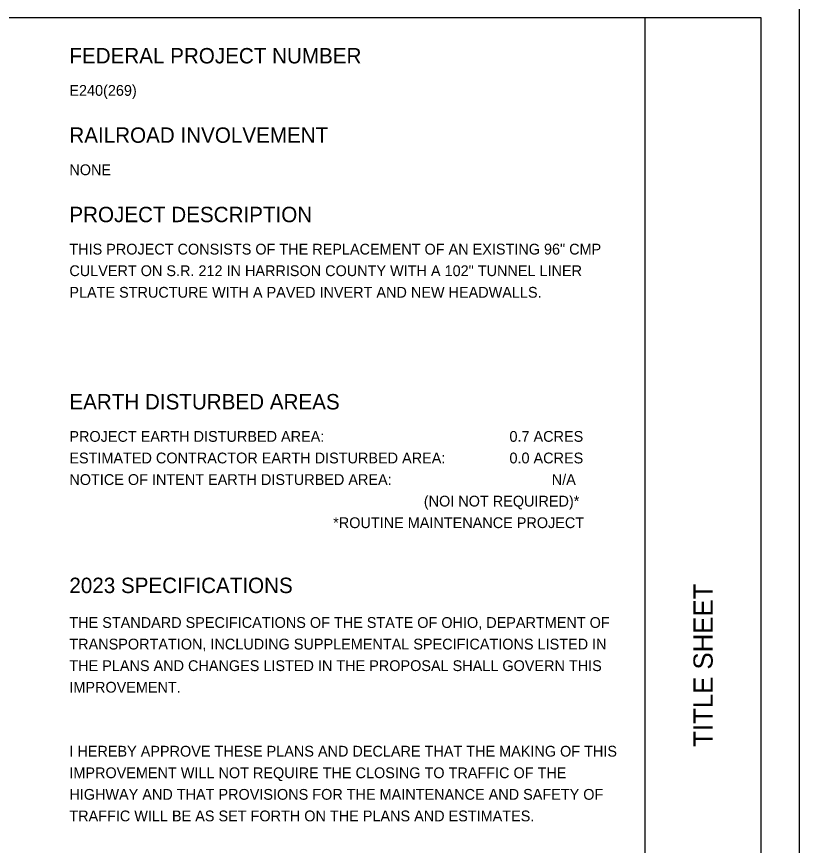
# Model space of a CAD drawing. Extents: x -19.9 to 41.9, y 0 to 32.3.
# Drawn here: x 23.84 to 34, y 10.76 to 21.51 of the extents above; entities that cross this region are included whole.
import ezdxf

# ---------------------------------------------------------------- set-up
doc = ezdxf.new("R2010")
doc.units = 0
for name, color, linetype in [('SH_Border', 7, 'Continuous'), ('SH_Cut_Line', 7, 'Continuous'), ('SH_Data', 7, 'Continuous'), ('SH_Text', 7, 'Continuous')]:
    doc.layers.add(name, color=color, linetype=linetype)

msp = doc.modelspace()

# ---------------------------------------------------------------- linework, layer by layer
at = {"layer": 'SH_Border'}
msp.add_line((32, 0.5), (32, 21.5), dxfattribs=at)
msp.add_lwpolyline([(1.5, 21.5), (33.5, 21.5), (33.5, 0.5), (1.5, 0.5)], close=True, dxfattribs=at)
at = {"layer": 'SH_Cut_Line'}
msp.add_lwpolyline([(0, 0), (34, 0), (34, 22), (0, 22)], close=True, dxfattribs=at)

# ---------------------------------------------------------------- texts
at = {"layer": 'SH_Data'}
msp.add_text('TITLE SHEET', height=0.25, rotation=90, dxfattribs=at).set_placement((32.875, 12.035))
at = {"layer": 'SH_Text'}
for s, height, p in [('FEDERAL PROJECT NUMBER', 0.2, (24.528, 20.903)), ('E240(269)', 0.14, (24.528, 20.483)), ('RAILROAD INVOLVEMENT', 0.2, (24.528, 19.873)), ('NONE', 0.14, (24.528, 19.453)), ('PROJECT DESCRIPTION', 0.2, (24.528, 18.843)), ('THIS PROJECT CONSISTS OF THE REPLACEMENT OF AN EXISTING 96" CMP ', 0.14, (24.528, 18.423)), ('CULVERT ON S.R. 212 IN HARRISON COUNTY WITH A 102" TUNNEL LINER ', 0.14, (24.528, 18.143)), ('PLATE STRUCTURE WITH A PAVED INVERT AND NEW HEADWALLS.', 0.14, (24.528, 17.863)), ('EARTH DISTURBED AREAS', 0.2, (24.528, 16.413)), ('PROJECT EARTH DISTURBED AREA:', 0.14, (24.528, 15.993)), ('0.7 ACRES', 0.14, (30.238, 15.993)), ('ESTIMATED CONTRACTOR EARTH DISTURBED AREA:', 0.14, (24.528, 15.713)), ('0.0 ACRES', 0.14, (30.238, 15.713)), ('NOTICE OF INTENT EARTH DISTURBED AREA:', 0.14, (24.528, 15.433)), ('N/A', 0.14, (30.787, 15.433)), ('(NOI NOT REQUIRED)*', 0.14, (29.127, 15.153)), ('*ROUTINE MAINTENANCE PROJECT', 0.14, (27.951, 14.873)), ('2023 SPECIFICATIONS', 0.2, (24.528, 14.03)), ('THE STANDARD SPECIFICATIONS OF THE STATE OF OHIO, DEPARTMENT OF ', 0.14, (24.528, 13.578)), ('TRANSPORTATION, INCLUDING SUPPLEMENTAL SPECIFICATIONS LISTED IN ', 0.14, (24.528, 13.298)), ('THE PLANS AND CHANGES LISTED IN THE PROPOSAL SHALL GOVERN THIS ', 0.14, (24.528, 13.018)), ('IMPROVEMENT.', 0.14, (24.528, 12.738)), ('I HEREBY APPROVE THESE PLANS AND DECLARE THAT THE MAKING OF THIS ', 0.14, (24.528, 11.908)), ('IMPROVEMENT WILL NOT REQUIRE THE CLOSING TO TRAFFIC OF THE ', 0.14, (24.528, 11.628)), ('HIGHWAY AND THAT PROVISIONS FOR THE MAINTENANCE AND SAFETY OF ', 0.14, (24.528, 11.348)), ('TRAFFIC WILL BE AS SET FORTH ON THE PLANS AND ESTIMATES.', 0.14, (24.528, 11.068))]:
    msp.add_text(s, height=height, dxfattribs=at).set_placement(p)

doc.saveas('drawing.dxf')
